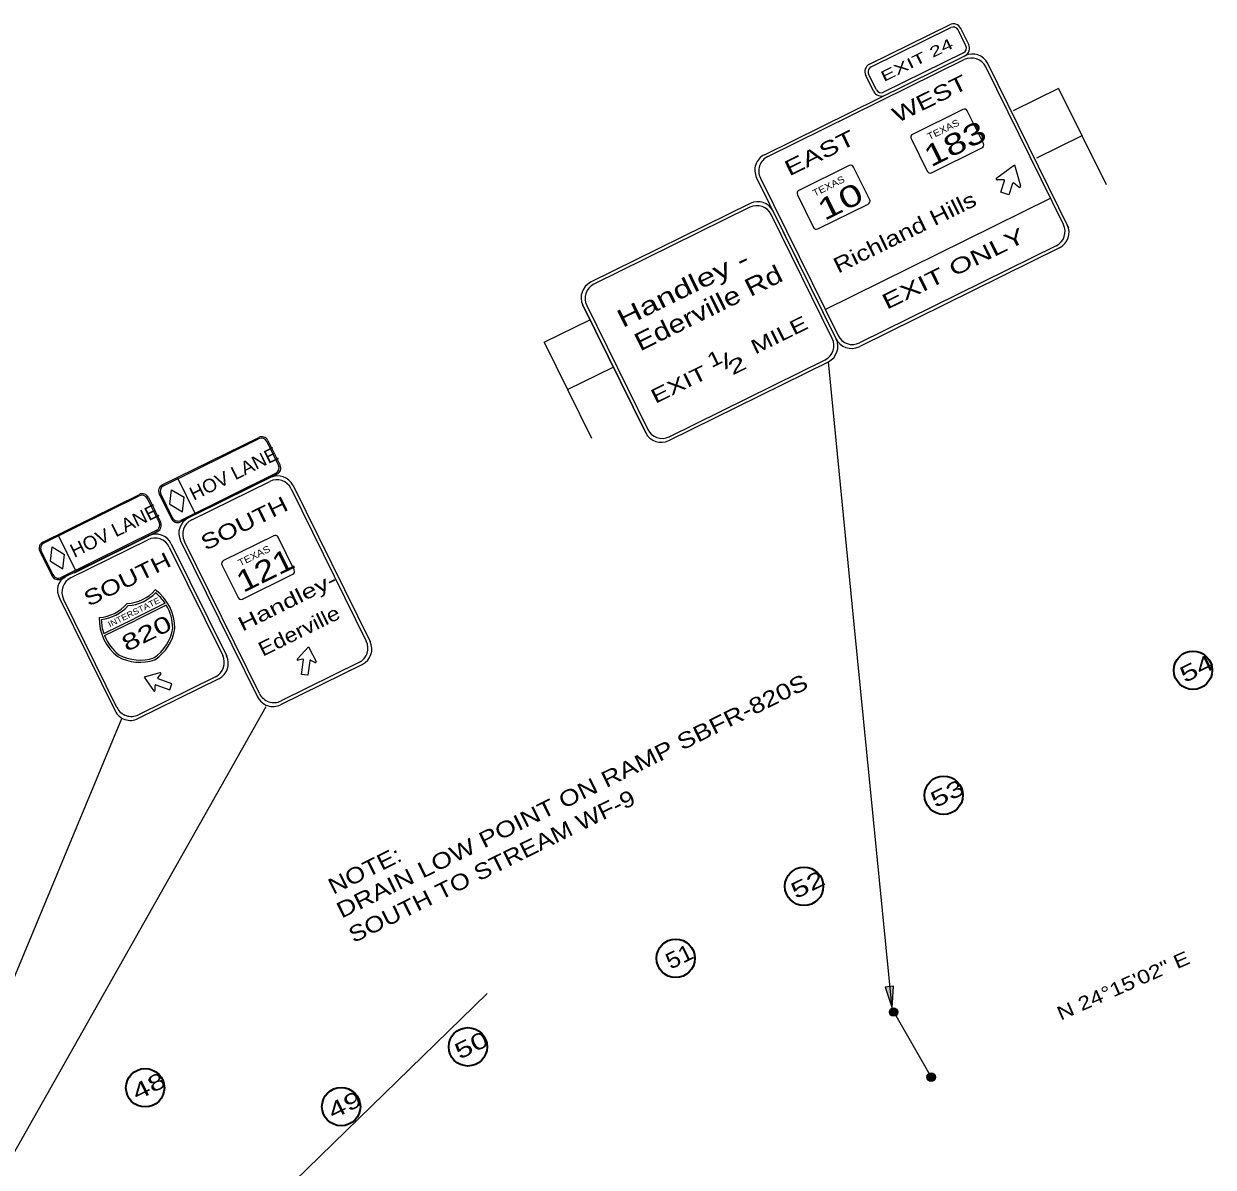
# Model space of a CAD drawing. Extents: x 2356431 to 2371438, y 6972864 to 6982525.
# Drawn here: x 2366966 to 2368009, y 6980671 to 6981673 of the extents above; entities that cross this region are included whole.
import ezdxf
from ezdxf.enums import TextEntityAlignment as Align

# ---------------------------------------------------------------- set-up
doc = ezdxf.new("R2010")
doc.units = 0
doc.header["$LTSCALE"] = 5.6
for name, color, linetype, lineweight in [('1', 7, 'Continuous', 25), ('17', 7, 'Continuous', 35), ('28', 7, 'Continuous', 35), ('48', 7, 'Continuous', 25), ('53', 7, 'Continuous', 13)]:
    doc.layers.add(name, color=color, linetype=linetype, lineweight=lineweight)
doc.layers.add('63', color=7, linetype='Continuous')

msp = doc.modelspace()

# ---------------------------------------------------------------- hatches: boundary and pattern name
at = {"layer": '1'}
for points in [[(2367727.67, 6980809.917), (2367728.754, 6980829.422), (2367721.611, 6980828.497)], [(2367732.699, 6980806.812, 1), (2367725.245, 6980806.451, 1)], [(2367765.586, 6980749.629, 1), (2367758.131, 6980749.268, 1)]]:
    msp.add_hatch(color=256, dxfattribs=at).paths.add_polyline_path(points)

# ---------------------------------------------------------------- linework, layer by layer
for p, q in [((2367707.93, 6981637.65), (2367777.889, 6981672.165)), ((2367709.172, 6981635.131), (2367779.129, 6981669.644)), ((2367792.241, 6981653.65), (2367785.405, 6981667.511)), ((2367794.768, 6981654.897), (2367787.929, 6981668.757)), ((2367615.634, 6981558.179), (2367791.358, 6981644.851)), ((2367618.548, 6981556.497), (2367790.904, 6981641.525)), ((2367790.114, 6981647.371), (2367720.155, 6981612.868)), ((2367713.876, 6981614.998), (2367707.044, 6981628.853)), ((2367877.829, 6981497.079), (2367809.743, 6981635.115)), ((2367882.605, 6981493.741), (2367811.424, 6981638.042)), ((2367711.35, 6981613.751), (2367704.522, 6981627.61)), ((2367873.457, 6981616.271), (2367833.693, 6981596.589)), ((2367873.457, 6981616.271), (2367915.17, 6981531.997)), ((2367894.039, 6981574.689), (2367854.274, 6981555.007)), ((2367678.56, 6981396.701), (2367608.815, 6981538.104)), ((2367612.166, 6981537.665), (2367680.242, 6981399.618)), ((2367603.27, 6981515.409), (2367463.359, 6981446.386)), ((2367602.833, 6981512.056), (2367466.279, 6981444.701)), ((2367675.202, 6981397.135), (2367621.665, 6981505.665)), ((2367678.545, 6981396.698), (2367623.352, 6981508.595)), ((2367874.352, 6981476.564), (2367698.637, 6981389.883)), ((2367871.431, 6981478.253), (2367699.079, 6981393.231)), ((2367456.539, 6981426.299), (2367511.737, 6981314.408)), ((2367459.892, 6981425.862), (2367513.426, 6981317.339)), ((2367422.701, 6981393.925), (2367462.52, 6981413.499)), ((2367422.701, 6981393.925), (2367464.184, 6981309.539)), ((2367443.17, 6981352.287), (2367482.987, 6981371.862)), ((2367531.83, 6981307.592), (2367671.728, 6981376.605)), ((2367532.267, 6981310.945), (2367668.815, 6981378.296)), ((2367116.709, 6981242.683), (2367188.411, 6981278.033)), ((2367113.664, 6981238.046), (2367182.004, 6981271.736)), ((2367200.837, 6981265.349), (2367266.689, 6981131.851)), ((2367202.519, 6981268.275), (2367270.041, 6981131.413)), ((2367010.87, 6981191.62), (2367083.743, 6981227.992)), ((2367007.402, 6981187.203), (2367075.165, 6981220.625)), ((2367093.997, 6981214.241), (2367140.826, 6981119.294)), ((2367095.678, 6981217.167), (2367144.339, 6981118.507)), ((2367103.934, 6981219.644), (2367171.434, 6981082.789)), ((2367173.126, 6981085.714), (2367107.272, 6981219.214)), ((2366997.979, 6981168.961), (2367046.464, 6981070.645)), ((2367048.157, 6981073.57), (2367001.317, 6981168.531)), ((2367263.885, 6981111.671), (2367191.518, 6981075.973)), ((2367260.828, 6981113.293), (2367191.959, 6981079.321)), ((2367137.366, 6981098.775), (2367066.271, 6981063.704)), ((2367134.444, 6981100.462), (2367066.988, 6981067.192)), ((2367731.026, 6980803.516), (2367761.858, 6980749.44))]:
    msp.add_line(p, q, dxfattribs=at)
at = {"layer": '1', "lineweight": 13}
for p, q in [((2367789.726, 6981597.795), (2367745.581, 6981576.024)), ((2367807.622, 6981567.881), (2367793.499, 6981596.526)), ((2367744.296, 6981572.258), (2367758.426, 6981543.626)), ((2367762.189, 6981542.349), (2367806.339, 6981564.123)), ((2367690.063, 6981548.617), (2367645.916, 6981526.834)), ((2367707.982, 6981518.7), (2367693.835, 6981547.35)), ((2367644.632, 6981523.078), (2367658.763, 6981494.436)), ((2367662.528, 6981493.152), (2367706.681, 6981514.939)), ((2367668.935, 6981422.546), (2367866.511, 6981520.017)), ((2367185.634, 6981224.129), (2367141.467, 6981202.347)), ((2367203.52, 6981194.204), (2367189.396, 6981222.851)), ((2367140.193, 6981198.579), (2367154.316, 6981169.934)), ((2367158.083, 6981168.659), (2367202.246, 6981190.436)), ((2367090.381, 6981164.954), (2367063.478, 6981151.68)), ((2367091.389, 6981163.339), (2367064.316, 6981149.986)), ((2367036.575, 6981138.409), (2367063.478, 6981151.68)), ((2367037.226, 6981136.617), (2367064.316, 6981149.986)), ((2366625.507, 6980094.921), (2367178.928, 6981074.442)), ((2366643.099, 6980079.535), (2367052.364, 6981064.006)), ((2367098.802, 6980556.492), (2367372.565, 6980822.722))]:
    msp.add_line(p, q, dxfattribs=at)
at = {"layer": '1'}
msp.add_lwpolyline([(2367511.737, 6981314.408), (2367456.539, 6981426.299), (2367493.767, 6981350.838)], dxfattribs=at)
at = {"layer": '1', "lineweight": 13}
msp.add_lwpolyline([(2367727.608, 6980810.09), (2367694.4, 6981146.757), (2367671.728, 6981376.605)], dxfattribs=at)
at = {"layer": '1'}
msp.add_lwpolyline([(2367727.67, 6980809.917), (2367728.754, 6980829.422), (2367721.611, 6980828.497)], close=True, dxfattribs=at)
for centre in [(2367728.972, 6980806.632), (2367761.859, 6980749.449)]:
    msp.add_circle(centre, 3.732, dxfattribs=at)
for centre, radius, start, end in [((2367781.206, 6981665.436), 7.501, 26.25603, 116.25603), ((2367781.206, 6981665.436), 4.688, 26.25603, 116.25603), ((2367788.041, 6981651.579), 4.688, 296.25603, 26.25603), ((2367788.041, 6981651.579), 7.501, 296.25603, 26.25603), ((2367797.132, 6981628.892), 14.063, 26.25267, 116.25267), ((2367797.984, 6981631.403), 15.001, 26.25267, 116.25267), ((2367711.247, 6981630.927), 7.501, 116.25603, 206.25603), ((2367711.247, 6981630.927), 4.688, 116.25603, 206.25603), ((2367718.082, 6981617.07), 7.501, 206.25603, 296.25603), ((2367718.082, 6981617.07), 4.688, 206.25603, 296.25603), ((2367622.266, 6981544.735), 15.001, 116.25209, 206.25209), ((2367624.777, 6981543.883), 14.063, 116.25209, 206.25209), ((2367609.904, 6981501.955), 15.001, 26.25647, 116.25647), ((2367609.052, 6981499.443), 14.063, 26.25648, 116.25648), ((2367865.217, 6981490.854), 14.063, 296.25268, 26.25268), ((2367867.728, 6981490.002), 15.001, 296.25268, 26.25268), ((2367469.993, 6981432.939), 15.001, 116.25647, 206.25647), ((2367472.505, 6981432.087), 14.063, 116.25647, 206.25647), ((2367692.86, 6981405.845), 14.063, 206.25209, 296.25209), ((2367662.589, 6981390.912), 14.063, 296.25648, 26.25648), ((2367665.1, 6981390.06), 15.001, 296.25648, 26.25648), ((2367692.008, 6981403.333), 15.001, 206.25209, 296.25209), ((2367526.042, 6981323.555), 14.063, 206.25648, 296.25648), ((2367525.19, 6981321.044), 15.001, 206.25647, 296.25647), ((2367189.077, 6981261.635), 15.001, 26.25695, 116.25695), ((2367188.225, 6981259.124), 14.063, 26.25695, 116.25695), ((2367117.375, 6981226.283), 15.001, 116.25695, 206.25695), ((2367119.886, 6981225.431), 14.063, 116.25695, 206.25695), ((2367082.237, 6981210.528), 15.001, 26.25695, 116.25695), ((2367081.385, 6981208.017), 14.063, 26.25695, 116.25695), ((2367013.932, 6981174.747), 14.063, 116.25695, 206.25695), ((2367254.078, 6981125.629), 14.063, 296.25695, 26.25695), ((2367256.589, 6981124.777), 15.001, 296.25695, 26.25695), ((2367128.221, 6981113.073), 14.063, 296.25695, 26.25695), ((2367130.732, 6981112.221), 15.001, 296.25695, 26.25695), ((2367211.131, 6981115.409), 0.506, 352.02585, 102.00896), ((2367217.749, 6981114.482), 0.506, 62.04274, 172.02585), ((2367084.329, 6981099.208), 0.506, 140.44865, 250.43176), ((2367184.887, 6981089.424), 15.001, 206.25695, 296.25695), ((2367185.739, 6981091.935), 14.063, 206.25695, 296.25695), ((2367059.916, 6981077.293), 15.001, 206.25695, 296.25695), ((2367060.768, 6981079.804), 14.063, 206.25695, 296.25695)]:
    msp.add_arc(centre, radius, start, end, dxfattribs=at)
at = {"layer": '1', "lineweight": 13}
for centre, radius, start, end in [((2367790.979, 6981595.285), 2.813, 26.25158, 116.25158), ((2367746.818, 6981573.506), 2.813, 116.25158, 206.25158), ((2367805.103, 6981566.646), 2.813, 296.25158, 26.25158), ((2367691.318, 6981546.098), 2.813, 26.25267, 116.25267), ((2367760.942, 6981544.867), 2.813, 206.25158, 296.25158), ((2367647.157, 6981524.318), 2.813, 116.25267, 206.25267), ((2367705.442, 6981517.459), 2.813, 296.25268, 26.25268), ((2367661.282, 6981495.679), 2.813, 206.25267, 296.25267), ((2367186.874, 6981221.602), 2.813, 26.25588, 116.25588), ((2367142.714, 6981199.82), 2.813, 116.25588, 206.25588), ((2367201, 6981192.964), 2.813, 296.25588, 26.25588), ((2367054.897, 6981200.603), 35.984, 273.43645, 318.28676), ((2367054.897, 6981200.603), 37.874, 274.63436, 315.6312), ((2367056.993, 6981142.795), 41.954, 0.11925, 53.82162), ((2367056.993, 6981142.795), 40.064, 33.56569, 51.43044), ((2367029.865, 6981188.256), 35.984, 274.22536, 319.07567), ((2367029.865, 6981188.256), 37.874, 276.88092, 317.87776), ((2367056.993, 6981142.795), 40.064, 0.33578, 30.84777), ((2367156.841, 6981171.182), 2.813, 206.25588, 296.25588), ((2367074.46, 6981151.41), 41.954, 178.6905, 232.39288), ((2367074.46, 6981151.41), 40.064, 181.08168, 198.94643), ((2367058.754, 6981149.274), 38.808, 304.0941, 350.74048), ((2367058.754, 6981149.274), 40.698, 303.72796, 350.96386), ((2367074.46, 6981151.41), 40.064, 201.66436, 232.17634), ((2367068.247, 6981153.956), 40.698, 241.54826, 288.78416), ((2367068.247, 6981153.956), 38.808, 241.77164, 288.41802)]:
    msp.add_arc(centre, radius, start, end, dxfattribs=at)
at = {"layer": '1'}
msp.add_ellipse((2367009.821, 6981174.288), major_axis=(-9.412, 11.91), ratio=0.848877, start_param=6.07270093, end_param=7.64349725, dxfattribs=at)
at = {"layer": '17'}
for centre in [(2367991.373, 6981106.237), (2367772.853, 6980996.66), (2367650.463, 6980916.822), (2367537.94, 6980853.697), (2367355.75, 6980776.123), (2367072.891, 6980740.206), (2367244.666, 6980723.726)]:
    msp.add_circle(centre, 16.828, dxfattribs=at)
at = {"layer": '48'}
for p, q in [((2367087.857, 6981268.662), (2367172.453, 6981310.386)), ((2367089.007, 6981268), (2367172.273, 6981309.076)), ((2367189.777, 6981286.118), (2367179.697, 6981306.553)), ((2367180.362, 6981307.702), (2367191.095, 6981285.944)), ((2367188.41, 6981278.034), (2367103.818, 6981236.301)), ((2367187.255, 6981278.699), (2367103.989, 6981237.623)), ((2367094.581, 6981251.766), (2367096.02, 6981264.433)), ((2367096.02, 6981264.433), (2367106.946, 6981257.864)), ((2367101.561, 6981274.193), (2367116.544, 6981243.816)), ((2366983.187, 6981218.624), (2367067.783, 6981260.349)), ((2366984.338, 6981217.962), (2367067.603, 6981259.039)), ((2367085.108, 6981236.081), (2367075.027, 6981256.517)), ((2367075.693, 6981257.666), (2367086.426, 6981235.907)), ((2367085.173, 6981260.748), (2367095.964, 6981238.87)), ((2367086.494, 6981260.575), (2367096.573, 6981240.138)), ((2367105.507, 6981245.197), (2367106.946, 6981257.864)), ((2367094.581, 6981251.766), (2367105.507, 6981245.197)), ((2366996.891, 6981224.155), (2367011.874, 6981193.779)), ((2367083.741, 6981227.996), (2366999.148, 6981186.264)), ((2367082.585, 6981228.662), (2366999.32, 6981187.585)), ((2366989.911, 6981201.727), (2366991.35, 6981214.395)), ((2366991.35, 6981214.395), (2367002.276, 6981207.827)), ((2366980.503, 6981210.711), (2366991.295, 6981188.833)), ((2366981.824, 6981210.538), (2366991.903, 6981190.101)), ((2366989.911, 6981201.727), (2367000.838, 6981195.16)), ((2367000.838, 6981195.16), (2367002.276, 6981207.827))]:
    msp.add_line(p, q, dxfattribs=at)
for centre, radius, start, end in [((2367174.73, 6981304.098), 5.54, 26.25314, 116.25314), ((2367175.066, 6981305.087), 5.909, 26.25314, 116.25314), ((2367184.805, 6981283.665), 5.54, 296.25314, 26.25314), ((2367185.794, 6981283.329), 5.909, 296.25314, 26.25314), ((2367090.472, 6981263.361), 5.909, 116.25256, 206.25256), ((2367091.461, 6981263.025), 5.54, 116.25256, 206.25256), ((2367070.06, 6981254.061), 5.54, 26.25314, 116.25314), ((2367070.396, 6981255.05), 5.909, 26.25314, 116.25314), ((2367080.136, 6981233.628), 5.54, 296.25314, 26.25314), ((2367081.125, 6981233.292), 5.909, 296.25314, 26.25314), ((2367101.205, 6981241.599), 5.909, 206.25256, 296.25256), ((2367101.541, 6981242.588), 5.54, 206.25256, 296.25256), ((2366985.802, 6981213.324), 5.909, 116.25256, 206.25256), ((2366986.791, 6981212.989), 5.54, 116.25256, 206.25256), ((2366996.535, 6981191.562), 5.909, 206.25256, 296.25256), ((2366996.871, 6981192.551), 5.54, 206.25256, 296.25256)]:
    msp.add_arc(centre, radius, start, end, dxfattribs=at)
at = {"layer": '53'}
for p, q in [((2367825.447, 6981536.153), (2367819.925, 6981536.033)), ((2367822.781, 6981525.426), (2367826.117, 6981535.243)), ((2367838.659, 6981529.673), (2367834.327, 6981533.135)), ((2367206.285, 6981116.311), (2367216.1, 6981126.8)), ((2367216.1, 6981126.8), (2367222.668, 6981114.017)), ((2367211.013, 6981115.895), (2367206.967, 6981115.031)), ((2367221.656, 6981112.975), (2367217.975, 6981114.914)), ((2367083.952, 6981099.517), (2367086.59, 6981102.734)), ((2367081.624, 6981088.758), (2367081.59, 6981092.896)), ((2367082.261, 6981093.389), (2367082.27, 6981093.381))]:
    msp.add_line(p, q, dxfattribs=at)
for points in [[(2367819.346, 6981537.878), (2367834.831, 6981549.18), (2367840.248, 6981530.787)], [(2367833.272, 6981532.818), (2367829.935, 6981522.981), (2367826.372, 6981524.204), (2367822.781, 6981525.426)], [(2367217.246, 6981114.539), (2367215.469, 6981101.782), (2367212.665, 6981102.177), (2367209.859, 6981102.582), (2367211.625, 6981115.326)], [(2367085.775, 6981103.937), (2367071.93, 6981100.07), (2367080.232, 6981088.347)], [(2367082.27, 6981093.381), (2367094.402, 6981089.087), (2367095.359, 6981091.758), (2367096.311, 6981094.426), (2367084.172, 6981098.727)]]:
    msp.add_lwpolyline(points, dxfattribs=at)
for centre, radius, start, end in [((2367819.916, 6981537.051), 1.012, 125.99497, 271.37611), ((2367825.479, 6981535.49), 0.675, 341.25648, 91.23958), ((2367833.917, 6981532.627), 0.675, 51.27337, 161.25647), ((2367839.281, 6981530.48), 1.012, 231.13684, 16.51798), ((2367206.813, 6981115.779), 0.759, 136.76434, 282.14548), ((2367222.002, 6981113.652), 0.759, 241.90622, 27.28736), ((2367085.997, 6981103.208), 0.759, 320.31212, 105.69326), ((2367080.86, 6981088.757), 0.759, 215.17025, 0.55139), ((2367082.091, 6981092.912), 0.506, 70.43176, 180.41486)]:
    msp.add_arc(centre, radius, start, end, dxfattribs=at)

# ---------------------------------------------------------------- texts
at = {"layer": '1'}
for s, height, rotation, width, p in [('EXIT 24', 9.188, 26.256, 1.55, (2367751.285, 6981637.093)), ('WEST', 13.5, 26.252, 1.35, (2367763.617, 6981601.258)), ('EAST', 13.5, 26.252, 1.4, (2367667.097, 6981553.651)), ('Richland Hills', 13.5, 26.252, 1.25, (2367741.644, 6981484.11)), ('EXIT ONLY', 13.5, 26.256, 1.45, (2367784.296, 6981452.315)), ('Handley -', 15.68, 26.256, 1.4, (2367547.698, 6981433.915)), ('Ederville Rd', 15.68, 26.256, 1.25, (2367569.989, 6981416.817)), ('MILE', 12.54, 26.256, 1.35, (2367631.416, 6981394.588)), ('1', 12.54, 26.256, 1.3, (2367574.747, 6981373.74)), ('/', 12.54, 26.256, 1.7, (2367584.961, 6981371.669)), ('2', 12.54, 26.256, 1.65, (2367594.447, 6981367.923)), ('EXIT', 12.54, 26.256, 1.4, (2367543.44, 6981351.19)), ('SOUTH', 13.5, 26.257, 1.3, (2367162.641, 6981228.986)), ('SOUTH', 13.5, 26.257, 1.3, (2367060.132, 6981179.951)), ('Handley-', 12.54, 26.331, 1.4, (2367200.183, 6981160.78)), ('Ederville', 12.54, 26.331, 1.2, (2367210.544, 6981135.136))]:
    msp.add_text(s, height=height, rotation=rotation, dxfattribs=dict(at, width=width)).set_placement(p, align=Align.CENTER)
for s, height, rotation, width, p in [('TEXAS', 6, 26.252, 1.15, (2367760.211, 6981570.865)), ('183', 18.75, 26.252, 1.35, (2367761.544, 6981546.942)), ('TEXAS', 6, 26.253, 1.15, (2367659.69, 6981521.263)), ('10', 18.75, 26.253, 1.45, (2367668.143, 6981499.911)), ('TEXAS', 6, 26.256, 1.15, (2367156.1, 6981197.182)), ('121', 18.75, 26.256, 1.25, (2367158.706, 6981173.882)), ('INTERSTATE', 5.198, 26.256, 1.15, (2367041.888, 6981143.731)), ('820', 14.18, 26.256, 1.45, (2367056.678, 6981122.194))]:
    msp.add_text(s, height=height, rotation=rotation, dxfattribs=dict(at, width=width)).set_placement(p)
at = {"layer": '17'}
for s, width, p in [('54', 1.45, (2367997.669, 6981101.538)), ('53', 1.45, (2367779.148, 6980991.96)), ('52', 1.45, (2367656.759, 6980912.122)), ('51', 1.15, (2367544.185, 6980848.975)), ('50', 1.45, (2367361.996, 6980771.399)), ('48', 1.45, (2367079.185, 6980735.507)), ('49', 1.45, (2367250.961, 6980719.027))]:
    msp.add_text(s, height=14, rotation=26.268, dxfattribs=dict(at, width=width)).set_placement(p, align=Align.CENTER)
at = {"layer": '28', "width": 1.25}
msp.add_text('N 24°15\'02" E', height=12, rotation=23.813, dxfattribs=at).set_placement((2367932.574, 6980824.298), align=Align.CENTER)
at = {"layer": '48', "width": 1.05}
for p in [(2367153.055, 6981273.283), (2367048.385, 6981223.247)]:
    msp.add_text('HOV LANE', height=11.82, rotation=26.252, dxfattribs=at).set_placement(p, align=Align.CENTER)
at = {"layer": '63'}
for s, width, p in [('DRAIN LOW POINT ON RAMP SBFR-820S', 1.25, (2367244.982, 6980888.379)), ('SOUTH TO STREAM WF-9', 1.2, (2367255.604, 6980866.857))]:
    msp.add_text(s, height=14, rotation=26.268, dxfattribs=dict(at, width=width)).set_placement(p)
at = {"layer": '63', "width": 1.2}
msp.add_text('NOTE:', height=14, rotation=26.268, dxfattribs=at).set_placement((2367268.471, 6980924.517), align=Align.CENTER)

doc.saveas('drawing.dxf')
